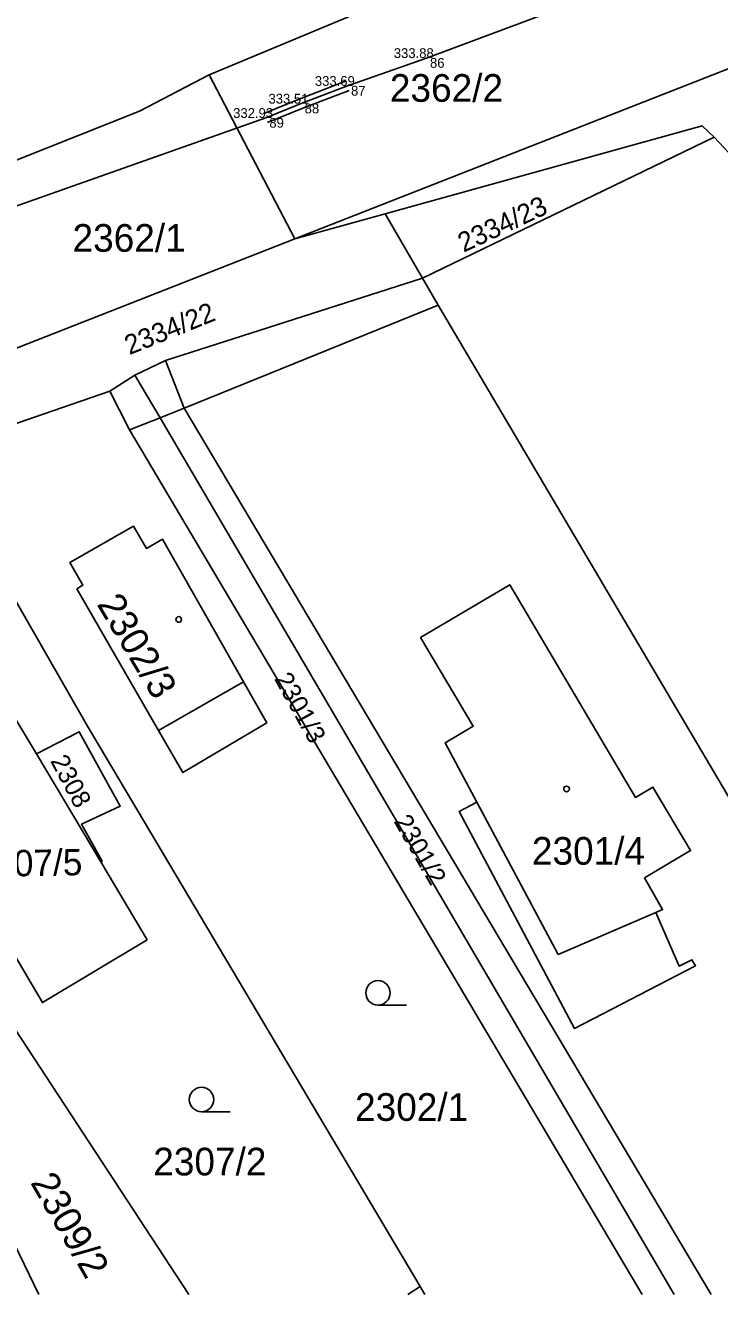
# Model space of a CAD drawing. Extents: x -606208 to -605570, y -1157873 to -1157573.
# Drawn here: x -605690.3 to -605647.7, y -1157764.5 to -1157686.5 of the extents above; entities that cross this region are included whole.
import ezdxf

# ---------------------------------------------------------------- set-up
doc = ezdxf.new("R2010")
doc.units = 0
for name, color, linetype in [('Vrstva 30', 7, 'Continuous'), ('Vrstva 38', 7, 'Continuous'), ('Vrstva 58', 7, 'Continuous'), ('Vrstva 59', 7, 'Continuous'), ('Vrstva 60', 7, 'Continuous'), ('Vrstva 62', 7, 'Continuous'), ('Vrstva 7', 7, 'Continuous')]:
    doc.layers.add(name, color=color, linetype=linetype)

msp = doc.modelspace()

# ---------------------------------------------------------------- linework, layer by layer
at = {"layer": 'Vrstva 30'}
msp.add_lwpolyline([(-605692.12, -1157698.06), (-605675.54, -1157692.21), (-605673.37, -1157691.33), (-605670.52, -1157690.24), (-605665.67, -1157688.53), (-605653.37, -1157683.93)], dxfattribs=at)
at = {"layer": 'Vrstva 38'}
for p, q in [((-605673.48, -1157691.05), (-605675.65, -1157691.93)), ((-605673.26, -1157691.61), (-605675.43, -1157692.49))]:
    msp.add_line(p, q, dxfattribs=at)
at = {"layer": 'Vrstva 60'}
for p, q in [((-605665.67, -1157688.53), (-605665.67, -1157688.53)), ((-605670.52, -1157690.24), (-605670.52, -1157690.24)), ((-605673.37, -1157691.33), (-605673.37, -1157691.33)), ((-605675.54, -1157692.21), (-605675.54, -1157692.21))]:
    msp.add_line(p, q, dxfattribs=at)
at = {"layer": 'Vrstva 62'}
for p, q in [((-605679.01, -1157689.56), (-605683.3, -1157691.79)), ((-605673.75, -1157699.63), (-605679.01, -1157689.56)), ((-605665.91, -1157702.05), (-605647.99, -1157693.4)), ((-605647.99, -1157693.4), (-605646.49, -1157694.99)), ((-605668.2, -1157698.09), (-605673.75, -1157699.63)), ((-605665.91, -1157702.05), (-605668.2, -1157698.09)), ((-605681.7, -1157707.11), (-605665.91, -1157702.05)), ((-605665.91, -1157702.05), (-605664.95, -1157703.71)), ((-605664.95, -1157703.71), (-605680.55, -1157710.03)), ((-605664.95, -1157703.71), (-605633.63, -1157756.72)), ((-605683.58, -1157708.01), (-605681.7, -1157707.11)), ((-605685.12, -1157708.99), (-605683.58, -1157708.01)), ((-605696.11, -1157712.79), (-605685.12, -1157708.99)), ((-605680.55, -1157710.03), (-605682.03, -1157710.63)), ((-605682.03, -1157710.63), (-605683.9, -1157711.37)), ((-605682.12, -1157729.83), (-605676.9, -1157726.84)), ((-605691.51, -1157728.12), (-605689.63, -1157731.27)), ((-605689.63, -1157731.27), (-605685.67, -1157737.9)), ((-605657.57, -1157743.59), (-605662.56, -1157734.23)), ((-605685.67, -1157737.9), (-605682.82, -1157742.68)), ((-605651.57, -1157741.01), (-605657.57, -1157743.59)), ((-605668.643, -1157746.69), (-605666.893, -1157746.69)), ((-605679.483, -1157753.24), (-605677.733, -1157753.24)), ((-605666.8, -1157764.47), (-605666.05, -1157763.97)), ((-605666.05, -1157763.97), (-605665.76, -1157764.47))]:
    msp.add_line(p, q, dxfattribs=at)
for points in [[(-605634.09, -1157680.59), (-605637.18, -1157684.66), (-605639.98, -1157686.4), (-605673.75, -1157699.63)], [(-605666.31, -1157683.93), (-605670.06, -1157685.83), (-605679.01, -1157689.56)], [(-605683.3, -1157691.79), (-605694.65, -1157696.29), (-605697.29, -1157697.32), (-605698.54, -1157697.8)], [(-605647.99, -1157693.4), (-605648.73, -1157692.69), (-605668.2, -1157698.09)], [(-605673.75, -1157699.63), (-605690.76, -1157706.31), (-605698.31, -1157709.27)], [(-605681.7, -1157707.11), (-605680.55, -1157710.03), (-605648.16, -1157764.47)], [(-605683.58, -1157708.01), (-605682.03, -1157710.63), (-605650.45, -1157764.47)], [(-605685.12, -1157708.99), (-605683.9, -1157711.37), (-605652.4, -1157764.47)], [(-605666.05, -1157763.97), (-605686.49, -1157729.56), (-605696.11, -1157712.79)], [(-605687.15, -1157721.12), (-605682.12, -1157729.83), (-605680.63, -1157732.41), (-605675.48, -1157729.35), (-605676.9, -1157726.84), (-605681.88, -1157718.08), (-605682.87, -1157718.65), (-605683.67, -1157717.27), (-605687.57, -1157719.51), (-605686.77, -1157720.9), (-605687.15, -1157721.12)], [(-605666.02, -1157724.11), (-605662.79, -1157729.57), (-605664.51, -1157730.58), (-605662.56, -1157734.23), (-605663.65, -1157734.8), (-605656.57, -1157748.12), (-605649.13, -1157744.27), (-605649.35, -1157743.91), (-605650.14, -1157744.29), (-605651.57, -1157741.01), (-605651.15, -1157740.83), (-605652.27, -1157738.88), (-605649.43, -1157737.2), (-605651.75, -1157733.3), (-605652.81, -1157733.95), (-605660.55, -1157720.88), (-605666.02, -1157724.11)], [(-605689.48, -1157764.47), (-605708.22, -1157725.77), (-605706.14, -1157724.71)], [(-605682.82, -1157742.68), (-605689.26, -1157746.54), (-605697.9, -1157731.89), (-605691.51, -1157728.12)], [(-605689.63, -1157731.27), (-605687, -1157729.9), (-605684.48, -1157734.47), (-605686.85, -1157735.57), (-605685.58, -1157737.85), (-605685.67, -1157737.9)], [(-605697.88, -1157737.54), (-605695.91, -1157740.61), (-605680.26, -1157764.47)]]:
    msp.add_lwpolyline(points, dxfattribs=at)
for centre, radius in [((-605680.887, -1157723.009), 0.175), ((-605657.057, -1157733.419), 0.175), ((-605668.643, -1157745.94), 0.75), ((-605679.483, -1157752.49), 0.75)]:
    msp.add_circle(centre, radius, dxfattribs=at)
at = {"layer": 'Vrstva 7'}
for p, q in [((-605670.63, -1157689.96), (-605673.48, -1157691.05)), ((-605670.41, -1157690.52), (-605673.26, -1157691.61))]:
    msp.add_line(p, q, dxfattribs=at)

# ---------------------------------------------------------------- texts
at = {"layer": 'Vrstva 58'}
for s, p in [('333.88 ', (-605667.67, -1157688.53)), ('333.69 ', (-605672.52, -1157690.24)), ('333.51 ', (-605675.37, -1157691.33)), ('332.93 ', (-605677.54, -1157692.21))]:
    msp.add_text(s, height=0.6, dxfattribs=at).set_placement(p)
at = {"layer": 'Vrstva 59'}
for s, p in [(' 86', (-605665.67, -1157689.13)), (' 87', (-605670.52, -1157690.84)), (' 88', (-605673.37, -1157691.93)), (' 89', (-605675.54, -1157692.81))]:
    msp.add_text(s, height=0.6, dxfattribs=at).set_placement(p)
at = {"layer": 'Vrstva 62'}
for s, p in [('2362/2', (-605667.91, -1157691.22)), ('2362/1', (-605687.41, -1157700.43)), ('2301/4', (-605659.182, -1157738.07)), ('2302/1', (-605670.05, -1157753.8)), ('2307/2', (-605682.45, -1157757.15))]:
    msp.add_text(s, height=1.7, dxfattribs=at).set_placement(p)
for s, height, rotation, p in [('2334/23', 1.2, 25, (-605663.38, -1157700.49)), ('2334/22', 1.2, 22, (-605683.91, -1157706.78)), ('2302/3', 1.7, 301, (-605685.95, -1157722.07)), ('2301/3', 1.139, 299, (-605675.04, -1157726.65)), ('2308', 1.139, 298, (-605688.797, -1157731.693)), ('2301/2', 1.139, 300, (-605667.7, -1157735.4)), ('2307/5', 1.618, 1, (-605693.408, -1157738.832)), ('2309/2', 1.7, 300, (-605690.03, -1157757.59))]:
    msp.add_text(s, height=height, rotation=rotation, dxfattribs=at).set_placement(p)

doc.saveas('drawing.dxf')
